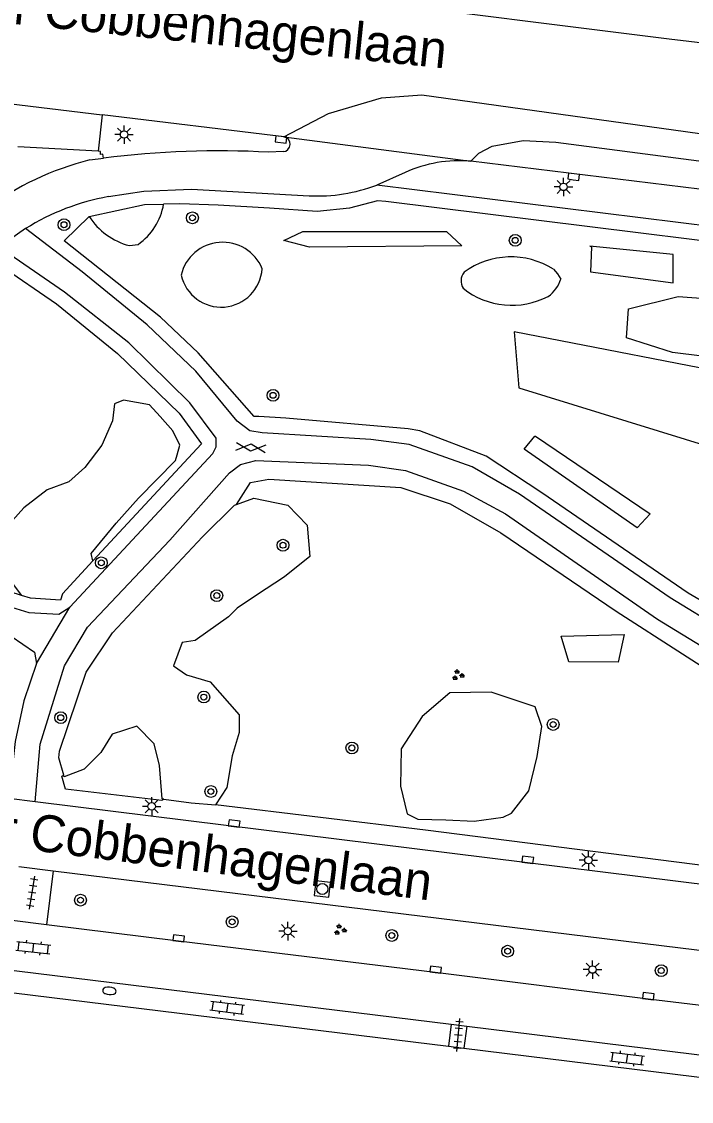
# Model space of a CAD drawing. Extents: x 131000 to 133014, y 396499 to 399001.
# Drawn here: x 131737.4 to 131782.7, y 396929.7 to 397002.7 of the extents above; entities that cross this region are included whole.
import ezdxf

# ---------------------------------------------------------------- set-up
doc = ezdxf.new("R2010")
doc.units = 0
for name, color, linetype in [('gg-anno-openbare ruimte label', 7, 'Continuous'), ('gg-bbg-hoofdgebouw', 7, 'Continuous'), ('gg-knt-verharding', 7, 'Continuous'), ('gg-knt-verharding nz', 7, 'Continuous'), ('gt-grn-groengrens', 7, 'Continuous'), ('gt-grn-weggrens', 7, 'Continuous'), ('gt-symb-boom', 7, 'Continuous'), ('gt-symb-brandkraan', 7, 'Continuous'), ('gt-symb-gesloten verharding', 7, 'Continuous'), ('gt-symb-groenvak', 7, 'Continuous'), ('gt-symb-klinker verharding', 7, 'Continuous'), ('gt-symb-kolk', 7, 'Continuous'), ('gt-symb-lichtmast', 7, 'Continuous'), ('gt-symb-rioolschacht', 7, 'Continuous'), ('gt-symb-tegel verharding', 7, 'Continuous')]:
    doc.layers.add(name, color=color, linetype=linetype)

# ---------------------------------------------------------------- blocks, each defined once
blk = doc.blocks.new('gt0-LMAST')
at = {"layer": 'gt-symb-lichtmast'}
for p, q in [((-0.182, 0.173), (-0.447, 0.438)), ((-0.005, 0.246), (-0.005, 0.621)), ((0.172, 0.173), (0.437, 0.438)), ((-0.255, -0.004), (-0.63, -0.004)), ((-0.182, -0.181), (-0.447, -0.446)), ((-0.005, -0.254), (-0.005, -0.629)), ((0.437, -0.446), (0.172, -0.181)), ((0.245, -0.004), (0.62, -0.004))]:
    blk.add_line(p, q, dxfattribs=at)
blk.add_circle((-0.005, -0.004), 0.25, dxfattribs=at)
blk = doc.blocks.new('gt0-KOLK')
at = {"layer": 'gt-symb-kolk'}
blk.add_lwpolyline([(0, 0), (0.375, 0), (0.375, 0.4), (-0.375, 0.4), (-0.375, 0), (0, 0)], dxfattribs=at)
blk = doc.blocks.new('gt0-BOOM')
at = {"layer": 'gt-symb-boom'}
for radius in [0.4, 0.2]:
    blk.add_circle((0, 0), radius, dxfattribs=at)
blk = doc.blocks.new('gt0-GRVAK')
at = {"layer": 'gt-symb-groenvak'}
for p, q in [((-0.11, 0.189), (-0.228, 0.24)), ((-0.182, 0.153), (0.088, 0.153)), ((-0.091, 0.211), (-0.156, 0.322)), ((-0.047, 0.214), (-0.047, 0.393)), ((-0.004, 0.211), (0.061, 0.322)), ((0.015, 0.189), (0.133, 0.24)), ((0.262, -0.052), (0.197, 0.059)), ((0.305, -0.049), (0.305, 0.13)), ((0.349, -0.052), (0.414, 0.059)), ((-0.245, -0.228), (-0.363, -0.177)), ((-0.318, -0.264), (-0.047, -0.264)), ((-0.226, -0.206), (-0.291, -0.095)), ((-0.183, -0.203), (-0.183, -0.024)), ((-0.139, -0.206), (-0.074, -0.095)), ((-0.12, -0.228), (-0.002, -0.177)), ((0.243, -0.074), (0.125, -0.023)), ((0.17, -0.11), (0.441, -0.11)), ((0.368, -0.074), (0.486, -0.023))]:
    blk.add_line(p, q, dxfattribs=at)
blk = doc.blocks.new('gt0-KL1')
at = {"layer": 'gt-symb-klinker verharding'}
for p, q in [((-1.15, 0.3), (1.15, 0.3)), ((-1, -0.3), (-1, 0.3)), ((-0.5, 0.3), (-0.5, 0.45)), ((0, -0.3), (0, 0.3)), ((0.5, 0.3), (0.5, 0.45)), ((1, -0.3), (1, 0.3)), ((-1.15, -0.3), (1.15, -0.3)), ((-0.5, -0.45), (-0.5, -0.3)), ((0.5, -0.45), (0.5, -0.3))]:
    blk.add_line(p, q, dxfattribs=at)
blk = doc.blocks.new('gt0-TEG1')
at = {"layer": 'gt-symb-tegel verharding'}
for p, q in [((-1.125, 0), (1.125, 0)), ((-0.9, -0.25), (-0.9, 0.25)), ((-0.45, -0.25), (-0.45, 0.25)), ((0, -0.25), (0, 0.25)), ((0.45, -0.25), (0.45, 0.25)), ((0.9, -0.25), (0.9, 0.25))]:
    blk.add_line(p, q, dxfattribs=at)
blk = doc.blocks.new('gt0-BR')
at = {"layer": 'gt-symb-brandkraan'}
for centre, radius, start, end in [((-0.244, 0), 0.206, 107.56694, 252.43307), ((0.599, -2.664), 3, 106.89205, 107.56694), ((0, -0.691), 0.938, 73.10799, 106.89205), ((-0.599, -2.664), 3, 72.43309, 73.10799), ((0.244, 0), 0.206, 287.56695, 72.43309), ((0.599, 2.664), 3, 252.43307, 253.10797), ((0, 0.691), 0.938, 253.10797, 286.89206), ((-0.599, 2.664), 3, 286.89206, 287.56695)]:
    blk.add_arc(centre, radius, start, end, dxfattribs=at)
blk = doc.blocks.new('gt0-GESVH1')
at = {"layer": 'gt-symb-gesloten verharding'}
for p, q in [((-0.992, -0.261), (0.008, 0.239)), ((0.008, -0.261), (-0.992, 0.239)), ((0.008, 0.239), (1.008, -0.261)), ((1.008, 0.239), (0.008, -0.261))]:
    blk.add_line(p, q, dxfattribs=at)
blk = doc.blocks.new('gt0-RS')
at = {"layer": 'gt-symb-rioolschacht'}
blk.add_lwpolyline([(-0.5, -0.5), (0.5, -0.5), (0.5, 0.5), (-0.5, 0.5)], close=True, dxfattribs=at)
blk.add_circle((0, 0), 0.375, dxfattribs=at)

msp = doc.modelspace()

# ---------------------------------------------------------------- linework, layer by layer
at = {"layer": 'gg-bbg-hoofdgebouw'}
for p, q in [((131731.024, 396937.776), (131766.297, 396933.434)), ((131766.297, 396933.434), (131767.336, 396933.306)), ((131767.336, 396933.306), (131796.599, 396929.702))]:
    msp.add_line(p, q, dxfattribs=at)
at = {"layer": 'gg-knt-verharding'}
for p, q in [((131731.558, 396997.757), (131742.888, 396996.391)), ((131755.156, 396994.911), (131742.888, 396996.391)), ((131742.603, 396993.932), (131737.184, 396994.24)), ((131755.156, 396994.911), (131767.81, 396993.27)), ((131755.106, 396993.91), (131754.156, 396993.877)), ((131742.041, 396993.346), (131742.976, 396993.47)), ((131841.827, 396984.136), (131767.81, 396993.27)), ((131763.35, 396992.5), (131761.448, 396991.653)), ((131844.269, 396981.372), (131761.448, 396991.653)), ((131737.71, 396988.707), (131735.892, 396987.462)), ((131738.349, 396949.957), (131736.583, 396950.176)), ((131807.106, 396941.425), (131738.349, 396949.957)), ((131737.259, 396945.581), (131739.568, 396945.298)), ((131739.568, 396945.298), (131739.119, 396941.643)), ((131739.568, 396945.298), (131805.672, 396937.178)), ((131739.119, 396941.643), (131736.811, 396941.932)), ((131731.206, 396939.249), (131766.48, 396934.914)), ((131766.48, 396934.914), (131766.297, 396933.434)), ((131766.48, 396934.914), (131767.518, 396934.778)), ((131767.518, 396934.778), (131767.336, 396933.306)), ((131767.518, 396934.778), (131796.781, 396931.179))]:
    msp.add_line(p, q, dxfattribs=at)
for points in [[(131742.976, 396993.47), (131742.927, 396993.738), (131742.774, 396993.707), (131742.762, 396993.923), (131742.603, 396993.932)], [(131743.31, 396990.87), (131745.7, 396991.24), (131748.91, 396991.37), (131756.88, 396990.93)], [(131835.207, 396957.16), (131833.098, 396956.47), (131830.266, 396956.46), (131826.117, 396957.517), (131822.698, 396959.048), (131820.045, 396960.021), (131816.087, 396960.679), (131812.974, 396959.949), (131807.488, 396956.971), (131802.166, 396956.956), (131794.945, 396957.354), (131788.337, 396959.418), (131781.271, 396963.742), (131771.079, 396970.748), (131767.883, 396972.611), (131763.626, 396974.106), (131761.037, 396974.458), (131753.692, 396974.89), (131752.86, 396975.028), (131752.017, 396975.679), (131749.209, 396979.07), (131745.924, 396982.198), (131741.522, 396985.79), (131737.71, 396988.707)], [(131740.7, 396963.117), (131750.371, 396973.497), (131750.593, 396973.948), (131750.581, 396974.549), (131748.804, 396976.932), (131744.676, 396980.996), (131740.34, 396984.415), (131735.892, 396987.462)], [(131729.372, 396984.074), (131728.426, 396981.219), (131724.638, 396972.945), (131722.824, 396968.101), (131734.396, 396963.835), (131737.929, 396962.756), (131739.95, 396962.634), (131740.7, 396963.117)], [(131668.49, 396981.96), (131674.94, 396975.8), (131679.208, 396972.45), (131681.969, 396970.537), (131686.365, 396968.26), (131690.513, 396966.966), (131694.524, 396966.521), (131697.502, 396966.625), (131704.282, 396968.182), (131708.524, 396968.83), (131711.928, 396968.731), (131721.02, 396966.702), (131726.885, 396964.722), (131736.742, 396961.158), (131738.318, 396960.068), (131738.445, 396959.3)], [(131738.349, 396949.957), (131738.683, 396953.843), (131740.329, 396959.151), (131741.895, 396961.759), (131747.449, 396967.646), (131751.499, 396972.187), (131752.228, 396972.755), (131753.273, 396973.024), (131760.892, 396972.726), (131763.388, 396972.364), (131767.299, 396970.95), (131770.148, 396969.427), (131780.411, 396962.311), (131787.525, 396957.959), (131794.405, 396955.633), (131802.646, 396954.999), (131806.98, 396955.116), (131808.739, 396954.688), (131809.437, 396953.597), (131809.659, 396952.801), (131809.672, 396948.844), (131807.106, 396941.425)], [(131738.445, 396959.3), (131737.586, 396956.775), (131736.994, 396954.023), (131736.583, 396950.176)], [(131805.498, 396934.72), (131801.539, 396935.347), (131795.864, 396934.641), (131793.652, 396934.936), (131779.78, 396936.612), (131765.39, 396938.411), (131748.034, 396940.526), (131739.119, 396941.643)]]:
    msp.add_lwpolyline(points, dxfattribs=at)
for centre, radius, start, end in [((131755.082, 396994.413), 0.503, 272.6999, 81.581), ((131746.799, 396974.282), 19.649, 104.01359, 126.79184), ((131767.062, 396984.302), 8.999, 85.2309, 114.35973), ((131757.445, 397002.152), 11.236, 267.11769, 290.87007), ((131746.095, 396975.329), 15.789, 100.16006, 122.07805)]:
    msp.add_arc(centre, radius, start, end, dxfattribs=at)
at = {"layer": 'gg-knt-verharding nz'}
msp.add_line((131742.888, 396996.391), (131742.603, 396993.932), dxfattribs=at)
for points in [[(131922.171, 396984.164), (131898.194, 396987.151), (131862.262, 396991.482), (131823.017, 396996.367), (131803.043, 396998.92), (131781.203, 397001.525), (131759.597, 397004.251), (131755.251, 397005.141), (131750.751, 397007.092), (131748.18, 397008.55), (131746.638, 397009.699)], [(131755.156, 396994.911), (131758.182, 396996.495), (131761.757, 396997.541), (131764.496, 396997.743), (131784.093, 396995.032), (131839.381, 396988.347), (131854.836, 396986.329), (131886.556, 396982.245), (131921.481, 396977.976)], [(131767.81, 396993.27), (131768.344, 396993.815), (131769.238, 396994.276), (131771.347, 396994.67), (131773.553, 396994.549), (131799.945, 396991.109), (131822.436, 396988.391), (131861.106, 396983.598), (131900.833, 396978.466), (131924.741, 396975.54)]]:
    msp.add_lwpolyline(points, dxfattribs=at)
msp.add_arc((131750.879, 396930.136), 63.825, 87.05697, 97.11282, dxfattribs=at)
at = {"layer": 'gt-grn-groengrens'}
msp.add_line((131744.72, 396987.556), (131745.316, 396987.636), dxfattribs=at)
for points in [[(131742, 396989.537), (131745.754, 396990.34), (131747.034, 396990.369)], [(131838.436, 396959.81), (131854.392, 396966.371), (131856.403, 396967.096), (131856.326, 396967.53), (131856.165, 396968.256), (131843.942, 396980.315), (131799.799, 396985.854), (131762.052, 396990.535), (131761.497, 396990.588), (131759.609, 396990.089), (131757.416, 396989.872), (131754.203, 396990.089), (131750.729, 396990.284), (131748.124, 396990.393), (131747.034, 396990.369)], [(131804.019, 396958.063), (131795.81, 396958.294), (131788.59, 396960.503), (131782.492, 396964.063), (131772.602, 396970.854), (131768.843, 396973.327), (131764.36, 396975.041), (131763.569, 396975.173), (131755.294, 396975.898), (131753.481, 396975.997), (131753.151, 396975.997), (131749.36, 396980.315), (131746.821, 396982.722), (131740.304, 396987.88), (131742, 396989.537)], [(131755.155, 396987.894), (131756.455, 396988.513), (131766.161, 396988.513), (131767.201, 396987.541), (131756.89, 396987.457), (131755.155, 396987.894)], [(131775.841, 396987.527), (131775.953, 396987.471), (131775.897, 396985.778), (131781.483, 396985.045), (131781.483, 396986.963), (131775.841, 396987.527)], [(131737.442, 396963.911), (131734.484, 396964.843), (131724.115, 396968.698), (131725.631, 396972.73), (131728.813, 396979.495), (131729.534, 396981.27), (131730.178, 396983.3), (131731.315, 396983.69), (131733.165, 396984.55), (131734.659, 396985.378), (131735.974, 396986.238), (131739.791, 396983.626), (131743.91, 396980.254), (131748.092, 396976.221), (131749.606, 396974.166), (131742.255, 396966.25)], [(131773.389, 396985.959), (131773.663, 396985.649), (131773.874, 396985.3)], [(131804.019, 396958.063), (131804.369, 396964.327), (131805.483, 396969.623), (131808.268, 396972.549), (131806.179, 396975.755), (131799.773, 396976.73), (131793.645, 396978.821), (131781.435, 396980.33), (131778.326, 396981.329), (131778.465, 396983.28), (131781.808, 396984.117), (131797.266, 396983.002), (131804.508, 396980.772), (131813.56, 396980.075), (131816.485, 396975.058), (131814.117, 396970.041), (131816.346, 396965.442), (131825.259, 396961.958), (131828.88, 396961.819), (131830.829, 396965.163), (131836.539, 396967.393), (131837.636, 396963.537), (131838.436, 396959.81)], [(131802.658, 396968.193), (131803.655, 396975.337), (131770.724, 396981.727), (131771.047, 396977.954), (131802.658, 396968.193)], [(131742.255, 396966.25), (131742.134, 396966.733), (131743.832, 396968.795), (131745.347, 396970.493), (131747.832, 396973.041), (131747.953, 396973.405), (131748.135, 396974.072), (131747.65, 396975.042), (131746.802, 396976.013), (131746.074, 396976.801), (131744.317, 396977.105), (131743.71, 396976.862), (131743.589, 396975.71), (131742.862, 396974.072), (131741.71, 396972.556), (131740.619, 396971.585), (131739.164, 396971.039), (131737.588, 396969.826), (131736.437, 396968.552), (131735.952, 396967.703), (131736.315, 396967.157), (131736.497, 396965.944), (131736.8, 396964.731), (131737.442, 396963.911)], [(131771.413, 396973.797), (131772.128, 396974.671), (131772.168, 396974.671), (131779.915, 396969.427), (131779.041, 396968.473), (131771.413, 396973.797)], [(131751.961, 396970.065), (131752.904, 396971.554), (131754.157, 396971.763), (131763.066, 396971.206), (131766.406, 396970.093), (131769.817, 396968.144), (131777.612, 396962.854), (131786.59, 396957.078), (131794.037, 396954.433), (131794.698, 396954.405)], [(131751.961, 396970.065), (131753.136, 396970.49), (131755.44, 396970.017), (131756.739, 396968.657), (131756.916, 396966.53), (131755.203, 396965.17), (131753.313, 396963.929), (131752.014, 396963.042), (131751.423, 396962.451), (131749.179, 396960.856), (131748.293, 396960.737), (131747.702, 396959.141), (131748.588, 396958.55), (131750.183, 396958.078), (131752.132, 396955.832), (131752.132, 396954.65), (131751.659, 396953.054), (131751.305, 396950.926), (131750.547, 396949.759)], [(131740.289, 396951.747), (131739.965, 396952.936), (131740.003, 396953.369), (131741.793, 396958.72), (131743.582, 396961.38), (131749.675, 396967.86), (131751.835, 396970.02), (131751.961, 396970.065)], [(131742.255, 396966.25), (131740.193, 396964.026), (131740.059, 396963.598), (131738.033, 396963.727), (131737.442, 396963.911)], [(131773.9, 396961.145), (131778.157, 396961.262), (131777.765, 396959.397), (131774.417, 396959.428), (131773.9, 396961.145)], [(131763.051, 396951.01), (131763.495, 396949.143), (131764.216, 396948.782), (131766.116, 396948.743), (131768.026, 396948.654), (131769.98, 396948.921), (131770.558, 396949.187), (131771.713, 396950.698), (131772.29, 396953.01), (131772.601, 396955.054), (131772.157, 396956.388), (131769.181, 396957.366), (131766.382, 396957.321), (131764.516, 396955.721), (131763.095, 396953.543), (131763.051, 396951.01)], [(131747.054, 396950.141), (131746.934, 396950.158), (131746.757, 396952.404), (131746.403, 396953.881), (131745.221, 396955.063), (131743.568, 396954.531), (131742.8, 396953.29), (131741.677, 396952.167), (131740.319, 396951.635), (131740.289, 396951.747)], [(131747.054, 396950.141), (131746.919, 396950.048), (131740.411, 396950.814), (131740.168, 396951.684), (131740.289, 396951.747)], [(131747.054, 396950.141), (131748.896, 396949.881), (131750.537, 396949.744), (131750.547, 396949.759)], [(131783.994, 396945.578), (131764.736, 396948.03), (131750.547, 396949.759)]]:
    msp.add_lwpolyline(points, dxfattribs=at)
for centre, radius, start, end in [((131742.906, 396991.057), 4.185, 305.16024, 350.53173), ((131745.935, 396992.082), 4.686, 212.89411, 254.97352), ((131751.026, 396984.898), 2.885, 22.32714, 166.61271), ((131770.514, 396981.428), 5.367, 57.60545, 126.25764), ((131750.927, 396986.172), 2.774, 192.62747, 274.47155), ((131750.927, 396986.173), 2.774, 274.47535, 356.30508), ((131768.08, 396985.17), 0.944, 141.66891, 211.77202), ((131771.754, 396985.934), 2.213, 305.1227, 343.35156), ((131770.575, 396988.825), 5.302, 231.54665, 297.54353)]:
    msp.add_arc(centre, radius, start, end, dxfattribs=at)
at = {"layer": 'gt-grn-weggrens'}
msp.add_line((131738.445, 396959.3), (131740.7, 396963.117), dxfattribs=at)

# ---------------------------------------------------------------- block references
at = {"layer": 'gt-symb-boom'}
for p in [(131740.302, 396988.97), (131748.984, 396989.437), (131770.799, 396987.913), (131754.432, 396977.434), (131755.103, 396967.301), (131742.824, 396966.115), (131750.628, 396963.898), (131749.753, 396957.037), (131740.082, 396955.644), (131773.363, 396955.184), (131750.228, 396950.654), (131741.419, 396943.309), (131751.668, 396941.839), (131762.457, 396940.918), (131770.288, 396939.856), (131780.668, 396938.546)]:
    msp.add_blockref('gt0-BOOM', p, dxfattribs=at)
at = {"layer": 'gt-symb-boom', "rotation": -113.4620002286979}
msp.add_blockref('gt0-BOOM', (131759.76, 396953.597), dxfattribs=at)
at = {"layer": 'gt-symb-brandkraan', "rotation": -3.949350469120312}
msp.add_blockref('gt0-BR', (131743.372, 396937.176), dxfattribs=at)
at = {"layer": 'gt-symb-gesloten verharding', "rotation": -4.530520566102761}
msp.add_blockref('gt0-GESVH1', (131752.924, 396973.919), dxfattribs=at)
at = {"layer": 'gt-symb-groenvak'}
for p in [(131766.916, 396958.52), (131758.947, 396941.305)]:
    msp.add_blockref('gt0-GRVAK', p, dxfattribs=at)
at = {"layer": 'gt-symb-klinker verharding'}
for p, rotation in [((131738.23, 396940.092), -6.200970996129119), ((131751.332, 396936.022), 172.99574075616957), ((131778.364, 396932.603), -7.004259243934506)]:
    msp.add_blockref('gt0-KL1', p, dxfattribs=dict(at, rotation=rotation))
at = {"layer": 'gt-symb-kolk'}
for p, rotation in [((131754.997, 396994.931), 172.9957407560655), ((131774.72, 396992.016), -7.004259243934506), ((131751.779, 396948.295), -7.004259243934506), ((131771.625, 396945.832), -7.00425924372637), ((131748.034, 396940.526), -6.948854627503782), ((131765.39, 396938.411), -7.120011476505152), ((131779.78, 396936.612), -6.891806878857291)]:
    msp.add_blockref('gt0-KOLK', p, dxfattribs=dict(at, rotation=rotation))
at = {"layer": 'gt-symb-lichtmast'}
for p in [(131744.367, 396995.068), (131774.07, 396991.528), (131746.235, 396949.654), (131775.75, 396946.02), (131755.442, 396941.218), (131776.03, 396938.616)]:
    msp.add_blockref('gt0-LMAST', p, dxfattribs=at)
at = {"layer": 'gt-symb-rioolschacht', "rotation": 173.91299167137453}
msp.add_blockref('gt0-RS', (131757.767, 396944.062), dxfattribs=at)
at = {"layer": 'gt-symb-tegel verharding'}
for p, rotation in [((131738.153, 396943.814), 81.14057068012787), ((131766.955, 396934.187), 85.00791883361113)]:
    msp.add_blockref('gt0-TEG1', p, dxfattribs=dict(at, rotation=rotation))

# ---------------------------------------------------------------- texts
at = {"layer": 'gg-anno-openbare ruimte label'}
for rotation, p in [(354.1, (131723.711, 397003.906)), (352.8, (131722.786, 396948.621))]:
    msp.add_text('Professor Cobbenhagenlaan', height=2.5, rotation=rotation, dxfattribs=at).set_placement(p)

doc.saveas('drawing.dxf')
